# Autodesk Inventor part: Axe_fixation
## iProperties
Shininess: 20.0
Length Units: 11269
Angle Units: 11279
Time Units: 11290
Mass Units: 11283
Length Display Precision: 3
Angle Display Precision: 2
Created: 2004-05
Part Number: Axe_fixation
Material: Par défaut
Document SubType Name: Modélisation
Designer: Danielc
Density: 0.0
Volumn: 0.0
Area: 0.0
PropertySet Name: Model Information
Control State: 0
Master: False
Checked Out: False
Author: Danielc
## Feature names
1. Révolution1 [Revolution]
2. Chanfrein1 [Chamfer]
